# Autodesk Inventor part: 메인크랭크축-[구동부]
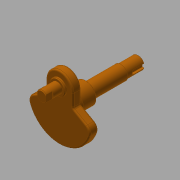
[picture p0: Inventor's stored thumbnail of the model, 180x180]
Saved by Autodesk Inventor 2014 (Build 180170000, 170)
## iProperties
Created: 2016-11
Part Number: 메인크랭크축-[구동부]
Material: 강철, 탄소
Document SubType Name: Modeling
Designer: mduedu
Density: 7.87 g/cm^3
Appearance: 주황색
Mass: 807.42 g
Surface Area: 206.102 cm^2
Volume: 102.595 cm^3
Author: mduedu
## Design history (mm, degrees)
sketch "스케치1" dims "d8" = 65
  geometry: L1 (-19, 26.368)-(-19, 8.368); L2 (-19, 8.368)-(-44.545, -6.381); L3 (0, 26.368)-(0, -45); L4 (19, 26.368)-(19, 8.368); L5 (19, 8.368)-(44.545, -6.381); C1 r 10 at (0, 0); C2 r 17.5 at (0, 0); A1 r 45 centre (0, 0) between (-44.545, -6.381) and (0, -45); A2 r 19 centre (0, 26.368) between (0, 45.368) and (-19, 26.368); A3 r 19 centre (0, 26.368) between (19, 26.368) and (0, 45.368); A4 r 45 centre (0, 0) between (0, -45) and (44.545, -6.381); 2 further points
  constraints: 10 end point, 8 point on circle, 6 centre point, 4 coincident, 3 symmetric about line, 2 point on line, 1 parallel, 1 tangent, 1 vertical, 1 vertical alignment, 5 other
  dimensions: "d1" = 20 diameter of C1; "d2" = 35 diameter of C2; "d4" = 18 distance of L1.start L1.end; "d5" = 120 deg angle of L2 L1; "d6" = 45 radius of A1; "d9" = 19 radius of A2
extrude "돌출1" new body sketch "스케치1" distance "d10" = 12; taper "d11" = 0 deg
extrude "돌출2" join sketch "스케치1" distance "d12" = 5; taper "d13" = 0 deg
extrude "돌출3" join sketch "스케치1" distance "d14" = 100; taper "d15" = 0 deg
sketch "스케치2"
  geometry: C1 r 7.5 at (0, 26.368); C2 r 11 at (0, 26.368); A1 r 19 centre (0, 26.368) between (19, 26.368) and (-19, 26.368) reference; 1 further point
  constraints: 2 centre point, 2 coincident
  dimensions: "d16" = 15 diameter of C1; "d17" = 22 diameter of C2
extrude "돌출4" join sketch "스케치2" distance "d18" = 3; taper "d19" = 0 deg
extrude "돌출5" join sketch "스케치2" distance "d20" = 25; taper "d21" = 0 deg
node "작업 평면1"
sketch "스케치3"
  geometry: L1 (-5.75, -4.815)-(5.75, -4.815); L2 (5.75, -4.815)-(5.75, 4.815); L3 (5.75, 4.815)-(-5.75, 4.815); L4 (-5.75, 4.815)-(-5.75, -4.815); L5 (-5.75, -4.815)-(5.75, 4.815); L6 (5.75, -4.815)-(-5.75, 4.815); A1 r 7.5 centre (0, 0) between (-5.75, 4.815) and (-5.75, -4.815); A2 r 7.5 centre (0, 0) between (5.75, -4.815) and (5.75, 4.815); 2 further points
  constraints: 12 end point, 4 point on circle, 2 centre point, 2 midpoint, 2 parallel, 1 coincident, 1 horizontal, 1 perpendicular, 2 other
  dimensions: "d23" = 11.5 distance between parallel lines of L2 L4
extrude "돌출6" cut sketch "스케치3" stored distance "d25" = 25; taper "d26" = 0 deg
fillet "모깎기1" dims "d27" = 3, "d29" = 10
fillet "모깎기2" dims "d28" = 2
sketch "스케치4"
  geometry: C1 r 15 at (0, 0); 1 further point
  constraints: 1 centre point, 1 coincident
  dimensions: "d30" = 30 diameter of C1
extrude "돌출7" join sketch "스케치4" distance "d31" = 21; taper "d32" = 0 deg
sketch "스케치5"
  geometry: C1 r 10 at (0, 0) reference; C2 r 9 at (0, 0); 1 further point
  constraints: 1 centre point
  dimensions: "d33" = 1 radial gap between concentric circles of C1 C2
extrude "돌출8" cut sketch "스케치5" distance "d34" = 25; taper "d35" = 0 deg
node "작업 평면2"
sketch "스케치6"
  geometry: L1 (-9, 0)-(9, 0) reference; L2 (-3, 0)-(3, 0); L3 (3, 0)-(3, 15); L4 (-3, 15)-(-3, 0); A1 r 3 centre (0, 15) between (3, 15) and (-3, 15); 1 further point
  constraints: 6 end point, 2 point on circle, 2 tangent, 1 centre point, 1 horizontal, 1 parallel, 1 perpendicular, 1 point on line, 1 vertical alignment
  dimensions: "d36" = 18 dimension on A1 L1; "d37" = 6 distance between parallel lines of L3 L4
extrude "돌출9" cut sketch "스케치6" distance "d38" = 3.5; taper "d39" = 0 deg
chamfer "모따기1" distance "d40" = 1; stored, may be unused: second distance "d41" = 2, angle "d42" = 45 deg
chamfer "모따기2" distance "d43" = 1; stored, may be unused: second distance "d44" = 2, angle "d45" = 45 deg
node "솔리드1"
node "투영된 루프1"
other parameters: "d3" = 38, "d22" = 13
